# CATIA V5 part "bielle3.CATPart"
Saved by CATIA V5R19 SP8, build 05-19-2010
Part number: bielle3
Bounding box of the stored display mesh (mm): x 0 to 110, y -119.864 to 119.864, z -833.809 to 1005.809
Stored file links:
  C:\Users\ThinkMotion\Desktop\EU_thinkMotion\iao\IAO_MMS_Groupe3\gdespas\projet_Thinkmotion_GDESPAS\projet Thinkmotion GDESPAS\Assemblage gdespas\bielle3.CATPart
  C:\Users\ThinkMotion\Desktop\EU_thinkMotion\iao\IAO_MMS_Groupe3\gdespas\projet_Thinkmotion_GDESPAS\projet Thinkmotion GDESPAS\Assemblage gdespas\Bielle2.CATPart
  C:\Users\ThinkMotion\Desktop\EU_thinkMotion\iao\IAO_MMS_Groupe3\gdespas\projet_Thinkmotion_GDESPAS\projet Thinkmotion GDESPAS\Assemblage gdespas\Assemblage IAO.CATProduct
  C:\Users\ThinkMotion\Desktop\EU_thinkMotion\iao\IAO_MMS_Groupe3\gdespas\projet_Thinkmotion_GDESPAS\projet Thinkmotion GDESPAS\Assemblage gdespas\bielle1.CATPart
  C:\Users\ThinkMotion\Desktop\EU_thinkMotion\iao\IAO_MMS_Groupe3\gdespas\projet_Thinkmotion_GDESPAS\projet Thinkmotion GDESPAS\Assemblage gdespas\pneu.CATPart
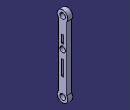
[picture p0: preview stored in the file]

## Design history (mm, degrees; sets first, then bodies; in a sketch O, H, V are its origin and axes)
External parameters (linked from other documents)
  External.diam_axe = 0.126
  External.entraxe_b3 = 1.6
Body1 (main body)
  Sketch1 on yz-plane, origin (0, 0, 0), H (0, 1, 0), V (0, 0, 1)
    construction line L1 through (0, 0) direction (0, 1)
    point P1 (0, -714)
    arc A1 centre (0, -714) radius 120 from (-97, -643.353) to (97, -643.353) ccw
    point P2 (0, 886)
    arc A2 centre (0, 886) radius 120 from (97, 815.353) to (-97, 815.353) ccw
    line L2 (-97, 815.353) -> (-97, -643.353)
    line L3 (97, 815.353) -> (97, -643.353)
    point P3 (0, 823)
    circle A3 centre (0, 886) radius 63
    circle A4 centre (0, -714) radius 63
    point P4 (0, 0)
    construction line L4 through (-553, -63.7799) direction (1, 0)
    reference intersected line E1 through (0, 0) direction (0, 1) from zx-plane
    reference intersected line E2 through (0, 0) direction (-1, 0) from xy-plane
    circle A5 centre (0, 224) radius 63
    point P9 (0, 224)
    point P10 (0, 161)
    line L5 (-25, 514) -> (25, 514)
    line L6 (25, 514) -> (25, 334)
    line L7 (25, 334) -> (-25, 334)
    line L8 (-25, 334) -> (-25, 514)
    point P15 (-25, 29)
    line L9 (-25, 29) -> (25, 29)
    line L10 (25, 29) -> (25, -311)
    line L11 (25, -311) -> (-25, -311)
    line L12 (-25, -311) -> (-25, 29)
    point P17 (25, -311)
    radius A1 = 120
    radius A2 = 120
    distance P2 P1 = 1600 {= External.entraxe_b3}
    distance L3 L2 = 194
    radius A4 = 63
    radius A3 = 63
    distance L1 L2 = 97
    distance E1 L3 = 97
    distance P1 E2 = 714
    distance P9 P2 = 662
    radius A3 = 63 {= External.diam_axe /2} (reference)
    radius A3 = 63 {= External.diam_axe /2} (reference)
    radius A5 = 63 {= External.diam_axe /2}
    distance L6 L3 = 72
    distance L8 L2 = 72
    distance P9 L7 = 110
    length L8 = 180
    length L12 = 340
    distance P9 L9 = 195
    coincidence: P1 L1, P2 L1, A3 P3, P3 L1, P9 L1, A5 P10, P10 L1, P15 L8, P17 L6
    vertical: L3 L1, L6 V, L8 V, L10 V, L12 V
    horizontal: L5 H, L7 H, L9 H, L11 H
  Pad1: profile Sketch1, direction (1, 0, 0), length 110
